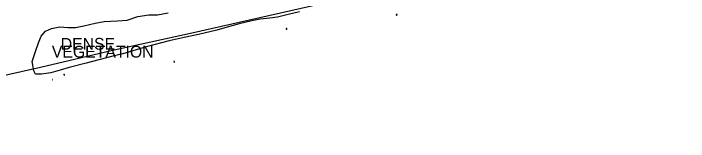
# Model space of a CAD drawing. Extents: x 2129547 to 2134906, y 657330 to 659734.
# Drawn here: x 2130531.7 to 2130932, y 657831.4 to 657907.3 of the extents above; entities that cross this region are included whole.
import ezdxf

# ---------------------------------------------------------------- set-up
doc = ezdxf.new("R2010")
doc.units = 0
for name, color, linetype in [('Default', 7, 'Continuous'), ('RD_X_Fence', 7, 'Continuous'), ('UT_X_Unknown_Cells', 7, 'Continuous'), ('VG_X_Cells', 7, 'Continuous'), ('VG_X_Text', 7, 'Continuous'), ('VG_X_Tree_Line_Lt', 7, 'Continuous')]:
    doc.layers.add(name, color=color, linetype=linetype)

# ---------------------------------------------------------------- blocks, each defined once
blk = doc.blocks.new('POINT_DISPLAY')
at = {"layer": 'Default'}
blk.add_line((0, 0), (0, 0), dxfattribs=at)

msp = doc.modelspace()

# ---------------------------------------------------------------- linework, layer by layer
at = {"layer": 'RD_X_Fence'}
msp.add_lwpolyline([(2130372.76, 657831.4), (2130401.89, 657841.24), (2130444.91, 657852.66), (2130493.65, 657863.34), (2130547.6, 657875.39), (2130589.68, 657885.4), (2130636.62, 657895.64), (2130749.57, 657921.43), (2130795.47, 657932.48), (2130846.52, 657944.86), (2130897.31, 657956.97), (2130898.55, 657989.46), (2130902.91, 657992.37), (2130925.34, 657969.73), (2130931.96, 657970.88)], dxfattribs=at)
at = {"layer": 'UT_X_Unknown_Cells'}
for p, q in [((2130554.6, 657868.06), (2130554.6, 657867.99)), ((2130554.65, 657868.06), (2130554.65, 657867.99))]:
    msp.add_line(p, q, dxfattribs=at)
msp.add_lwpolyline([(2130554.68, 657867.98), (2130554.68, 657868.06), (2130554.71, 657867.98), (2130554.74, 657868.06), (2130554.74, 657867.98)], dxfattribs=at)
for centre, radius, start, end in [((2130554.67, 657868.02), 0.1, 160.0169, 200.0392), ((2130554.67, 657868.02), 0.1, 100.0806, 140.0721), ((2130554.63, 657868.01), 0.0279, 205.1924, 334.8076), ((2130554.67, 657868.02), 0.1, 220.0577, 260.0473), ((2130554.67, 657868.02), 0.1, 40.0577, 80.1061), ((2130554.67, 657868.02), 0.1, 280.0114, 320.0264), ((2130554.67, 657868.02), 0.1, 340.0169, 20.0392)]:
    msp.add_arc(centre, radius, start, end, dxfattribs=at)
at = {"layer": 'VG_X_Cells'}
for centre in [(2130758.89, 657906.54), (2130693.65, 657898.2), (2130626.95, 657878.69), (2130561.7, 657871)]:
    msp.add_circle(centre, 0.012, dxfattribs=at)
for centre, radius, start, end in [((2130758.75, 657906.46), 0.0987, 96.1722, 320.5737), ((2130758.73, 657906.63), 0.0735, 39.0625, 279.5412), ((2130758.84, 657906.71), 0.0658, 354.0047, 205.9741), ((2130758.94, 657906.41), 0.114, 184.9476, 19.4572), ((2130758.99, 657906.68), 0.0776, 323.83, 165.0376), ((2130759.07, 657906.54), 0.0957, 259.1453, 101.4596), ((2130693.51, 657898.13), 0.0987, 96.1722, 320.5737), ((2130693.49, 657898.3), 0.0735, 39.0625, 279.5412), ((2130693.61, 657898.37), 0.0658, 354.0047, 205.9741), ((2130693.7, 657898.07), 0.114, 184.9476, 19.4572), ((2130693.75, 657898.35), 0.0776, 323.83, 165.0376), ((2130693.83, 657898.21), 0.0957, 259.1453, 101.4596), ((2130626.78, 657878.79), 0.0735, 39.0625, 279.5412), ((2130626.8, 657878.61), 0.0987, 96.1722, 320.5737), ((2130626.9, 657878.86), 0.0658, 354.0047, 205.9741), ((2130626.99, 657878.56), 0.114, 184.9476, 19.4572), ((2130627.04, 657878.83), 0.0776, 323.83, 165.0376), ((2130627.12, 657878.69), 0.0957, 259.1453, 101.4596), ((2130561.53, 657871.09), 0.0735, 39.0625, 279.5412), ((2130561.55, 657870.92), 0.0987, 96.1722, 320.5737), ((2130561.65, 657871.17), 0.0658, 354.0047, 205.9741), ((2130561.74, 657870.87), 0.114, 184.9476, 19.4572), ((2130561.79, 657871.14), 0.0776, 323.83, 165.0376), ((2130561.87, 657871), 0.0957, 259.1453, 101.4596)]:
    msp.add_arc(centre, radius, start, end, dxfattribs=at)
at = {"layer": 'VG_X_Tree_Line_Lt'}
msp.add_lwpolyline([(2130701.32, 657908.32), (2130693.81, 657906.49), (2130688.32, 657905.08), (2130683.67, 657904.47), (2130678.03, 657903.88), (2130673.03, 657903.01), (2130665.53, 657901.26), (2130658.38, 657899.27), (2130652.22, 657897.41), (2130641.4, 657894.84), (2130632.91, 657893.1), (2130624.07, 657891.06), (2130610.27, 657887.53), (2130602.38, 657885.17), (2130596.45, 657883.33), (2130590.62, 657882.03), (2130574.67, 657877.92), (2130564.76, 657875.24), (2130559.44, 657873.73), (2130553.8, 657872.18), (2130548.26, 657871.23), (2130544.73, 657871.41), (2130543.8, 657873.22), (2130542.81, 657878.75), (2130544.82, 657885.32), (2130546.57, 657889.83), (2130548.08, 657893.77), (2130550.63, 657896.91), (2130554.14, 657898.42), (2130559.21, 657899.36), (2130563.83, 657899.04), (2130568.34, 657898.93), (2130573.4, 657900.06), (2130580.08, 657901.47), (2130585.42, 657902.48), (2130593.4, 657902.9), (2130599.09, 657903.41), (2130605.43, 657905.49), (2130611.91, 657906.58), (2130616.99, 657906.51), (2130623.45, 657907.71)], dxfattribs=at)

# ---------------------------------------------------------------- block references
at = {"layer": 'UT_X_Unknown_Cells', "xscale": 3.9370000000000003, "yscale": 3.9370000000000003}
msp.add_blockref('POINT_DISPLAY', (2130554.67, 657868.02), dxfattribs=at)

# ---------------------------------------------------------------- texts
at = {"layer": 'VG_X_Text'}
for s, p in [('DENSE', (2130559.68, 657885.82)), ('VEGETATION', (2130554.42, 657881.16))]:
    msp.add_text(s, height=7, dxfattribs=at).set_placement(p)

doc.saveas('drawing.dxf')
